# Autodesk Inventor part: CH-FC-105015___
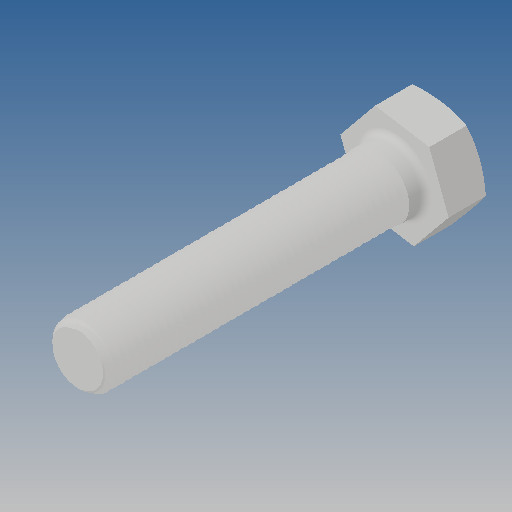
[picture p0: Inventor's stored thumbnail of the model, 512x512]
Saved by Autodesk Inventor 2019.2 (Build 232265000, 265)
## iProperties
Created: 2010-06
Part Number: CH-FC-105015___
Material: Ogólny
Document SubType Name: Modeling
Designer: CADENGINEERING4
Density: 1 g/cm^3
Appearance: Domyślna
Author: CADENGINEERING4
Revision Number: ANY
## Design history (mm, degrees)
feature "NONE"
node "Bryła1"
